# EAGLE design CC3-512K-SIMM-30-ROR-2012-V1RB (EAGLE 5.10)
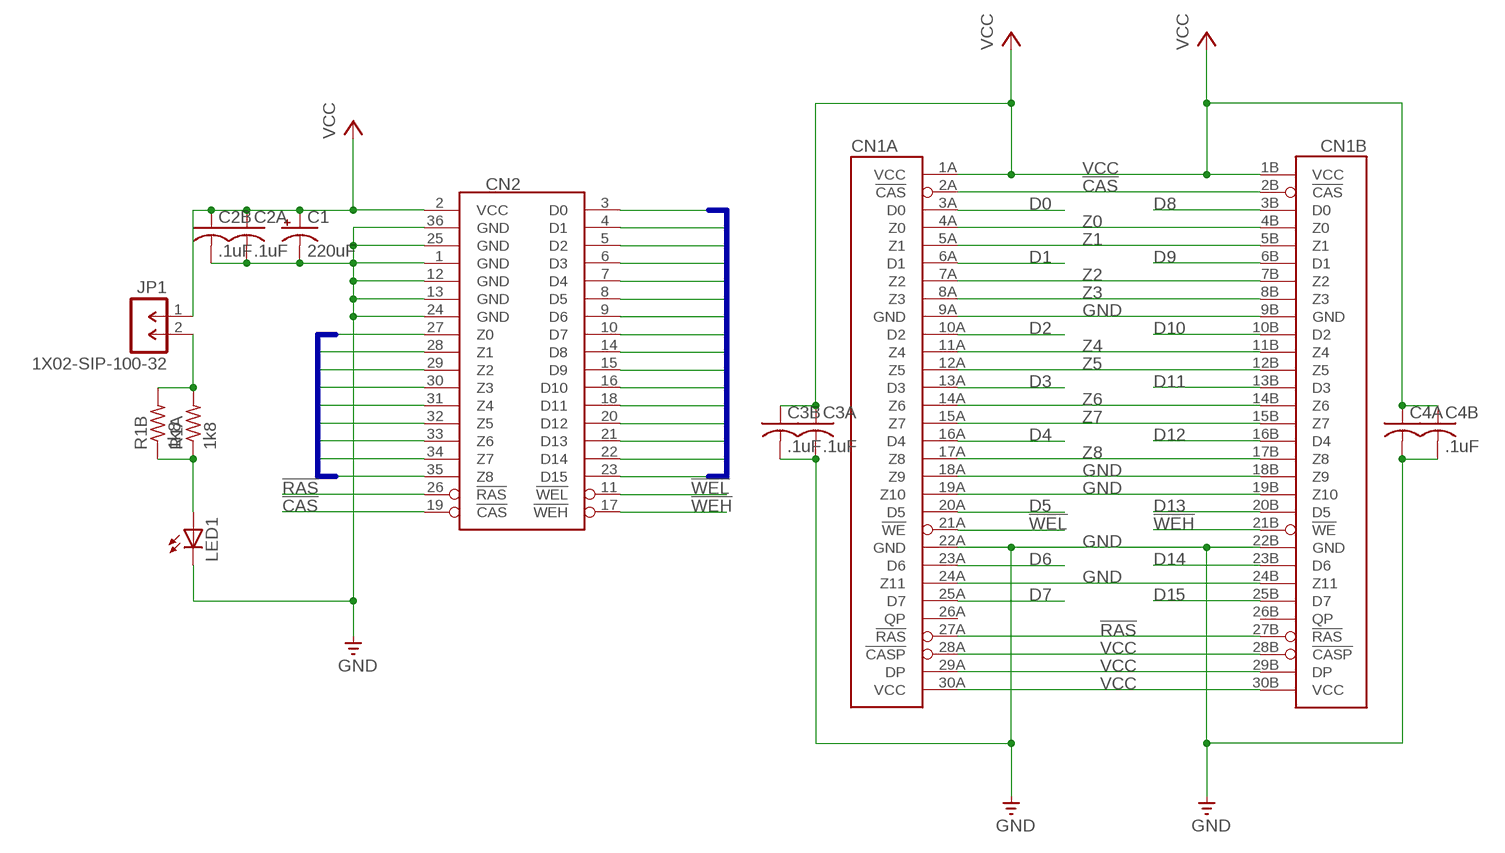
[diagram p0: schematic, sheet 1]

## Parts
C1  220uF  P-CAPACITOR-CPOL-RADIAL-1  [CPOL-RADIAL-1]
C2A  .1uF  NP-CAPACITOR-C050-025X075  [C050-025X075]
C2B  .1uF  NP-CAPACITOR-C1206K  [C1206K]
C3A  .1uF  NP-CAPACITOR-C050-025X075  [C050-025X075]
C3B  .1uF  NP-CAPACITOR-C1206K  [C1206K]
C4A  NP-CAPACITOR-C050-025X075  [C050-025X075]
C4B  .1uF  NP-CAPACITOR-C1206K  [C1206K]
CN1  DUAL-SIMM-30-UNIVERSAL-UNIVERSAL  [DUAL-SIMM-30-UNIVERSAL]
CN2  COCO3-MEMORY-EXPANSION-HEADER  [COCO3-MEMORY-EXPANSION-HEADER]
JP1  1X02-SIP-100-32  [SIL1X02-100]
LED1  LED5MM  [LED5MM]
R1A  1k8  RESISTOR  [0207/10]
R1B  1k8  RESISTOR-R1206  [R1206]

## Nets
!CAS: CN1.2A(A:!CAS) CN1.2B(B:!CAS) CN2.19(!CAS)
!RAS: CN1.27A(A:!RAS) CN1.27B(B:!RAS) CN2.26(!RAS)
!WEH: CN1.21B(B:!WE) CN2.17(!WEH)
!WEL: CN1.21A(A:!WE) CN2.11(!WEL)
D0: CN1.3A(A:D0) CN2.3(D0)
D1: CN1.6A(A:D1) CN2.4(D1)
D2: CN1.10A(A:D2) CN2.5(D2)
D3: CN1.13A(A:D3) CN2.6(D3)
D4: CN1.16A(A:D4) CN2.7(D4)
D5: CN1.20A(A:D5) CN2.8(D5)
D6: CN1.23A(A:D6) CN2.9(D6)
D7: CN1.25A(A:D7) CN2.10(D7)
D8: CN1.3B(B:D0) CN2.14(D8)
D9: CN1.6B(B:D1) CN2.15(D9)
D10: CN1.10B(B:D2) CN2.16(D10)
D11: CN1.13B(B:D3) CN2.18(D11)
D12: CN1.16B(B:D4) CN2.20(D12)
D13: CN1.20B(B:D5) CN2.21(D13)
D14: CN1.23B(B:D6) CN2.22(D14)
D15: CN1.25B(B:D7) CN2.23(D15)
GND [power]: C1.2(-) C2A.2(-) C2B.2(-) C3A.2(-) C3B.2(-) C4A.2(-) C4B.2(-) CN1.9A(A:GND) CN1.9B(B:GND) CN1.18A(A:Z9) CN1.18B(B:Z9) CN1.19A(A:Z10) CN1.19B(B:Z10) CN1.22A(A:GND) CN1.22B(B:GND) CN1.24A(A:Z11) CN1.24B(B:Z11) CN2.1(GND) CN2.12(GND) CN2.13(GND) CN2.24(GND) CN2.25(GND) CN2.36(GND) LED1.K(C)
N$45: LED1.A R1A.1 R1B.1
N$46: JP1.2 R1A.2 R1B.2
VCC [power]: C1.1(+) C2A.1(+) C2B.1(+) C3A.1(+) C3B.1(+) C4A.1(+) C4B.1(+) CN1.1A(A:VCC) CN1.1B(B:VCC) CN1.28A(A:!CASP) CN1.28B(B:!CASP) CN1.29A(A:DP) CN1.29B(B:DP) CN1.30A(A:VCC) CN1.30B(B:VCC) CN2.2(VCC) JP1.1
Z0: CN1.4A(A:Z0) CN1.4B(B:Z0) CN2.27(Z0)
Z1: CN1.5A(A:Z1) CN1.5B(B:Z1) CN2.28(Z1)
Z2: CN1.7A(A:Z2) CN1.7B(B:Z2) CN2.29(Z2)
Z3: CN1.8A(A:Z3) CN1.8B(B:Z3) CN2.30(Z3)
Z4: CN1.11A(A:Z4) CN1.11B(B:Z4) CN2.31(Z4)
Z5: CN1.12A(A:Z5) CN1.12B(B:Z5) CN2.32(Z5)
Z6: CN1.14A(A:Z6) CN1.14B(B:Z6) CN2.33(Z6)
Z7: CN1.15A(A:Z7) CN1.15B(B:Z7) CN2.34(Z7)
Z8: CN1.17A(A:Z8) CN1.17B(B:Z8) CN2.35(Z8)
Unconnected: CN1.26A(A:QP) CN1.26B(B:QP)

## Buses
D[0..15]
Z[0..8]

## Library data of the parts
C1 = GIMEchip-Capacitor:P-CAPACITOR: POLARIZED CAPACITOR
C2A C2B C3A C3B C4A C4B = GIMEchip-Capacitor:NP-CAPACITOR: NON-POLARIZED CAPACITOR
CN1 = GIMEchip-DRAM:DUAL-SIMM-30-UNIVERSAL
CN2 = GIMEchip-TRS-80-CoCo-3-Memory-Expansion-Connector:COCO3-MEMORY-EXPANSION-HEADER: Tandy Color Computer 3 Memory Expansion Connector Tandy Radio Shack TRS-80 Color Computer 3 Memory Expansion Header. CN6, CN5, CN4 on the CoCo 3 Motherboard. These connectors were intended, by Tandy, to upgrade the CoCo 3 from 128k RAM to 512k RAM. Used by third parties for expansion to: 256k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
JP1 = GIMEchip-Header-Generic:1X02: MALE HEADER
LED1 = adafruit:LED: LED
R1A R1B = GIMEchip-Resistor:RESISTOR

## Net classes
0 default: width 0.305 mm, clearance 0.203 mm
1 power: width 0.889 mm, clearance 0.203 mm

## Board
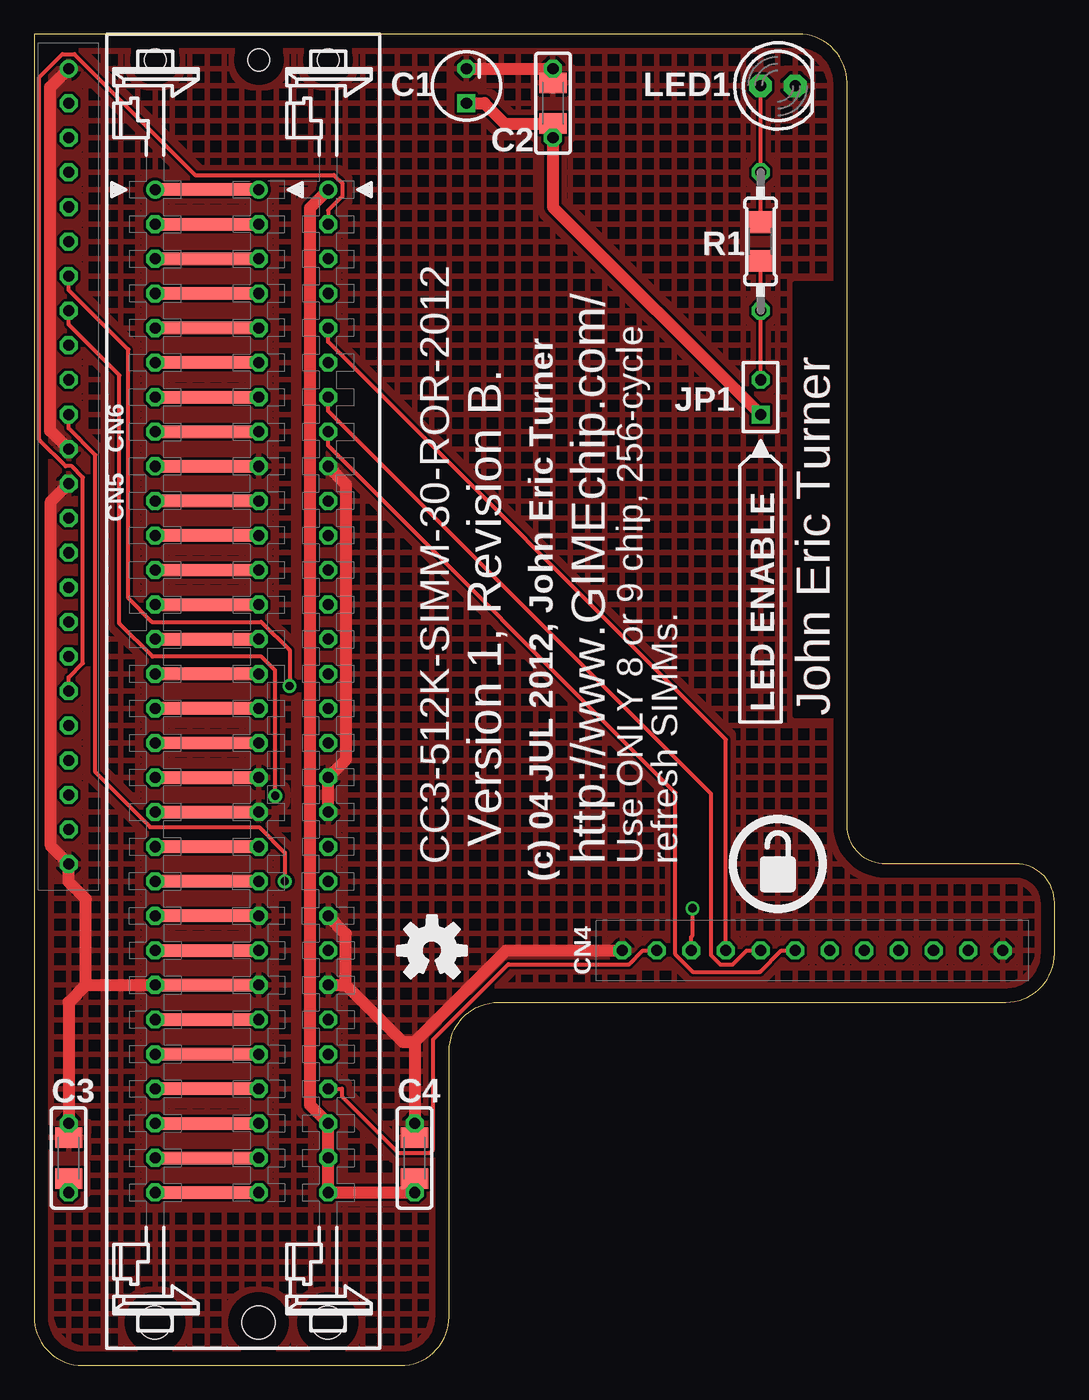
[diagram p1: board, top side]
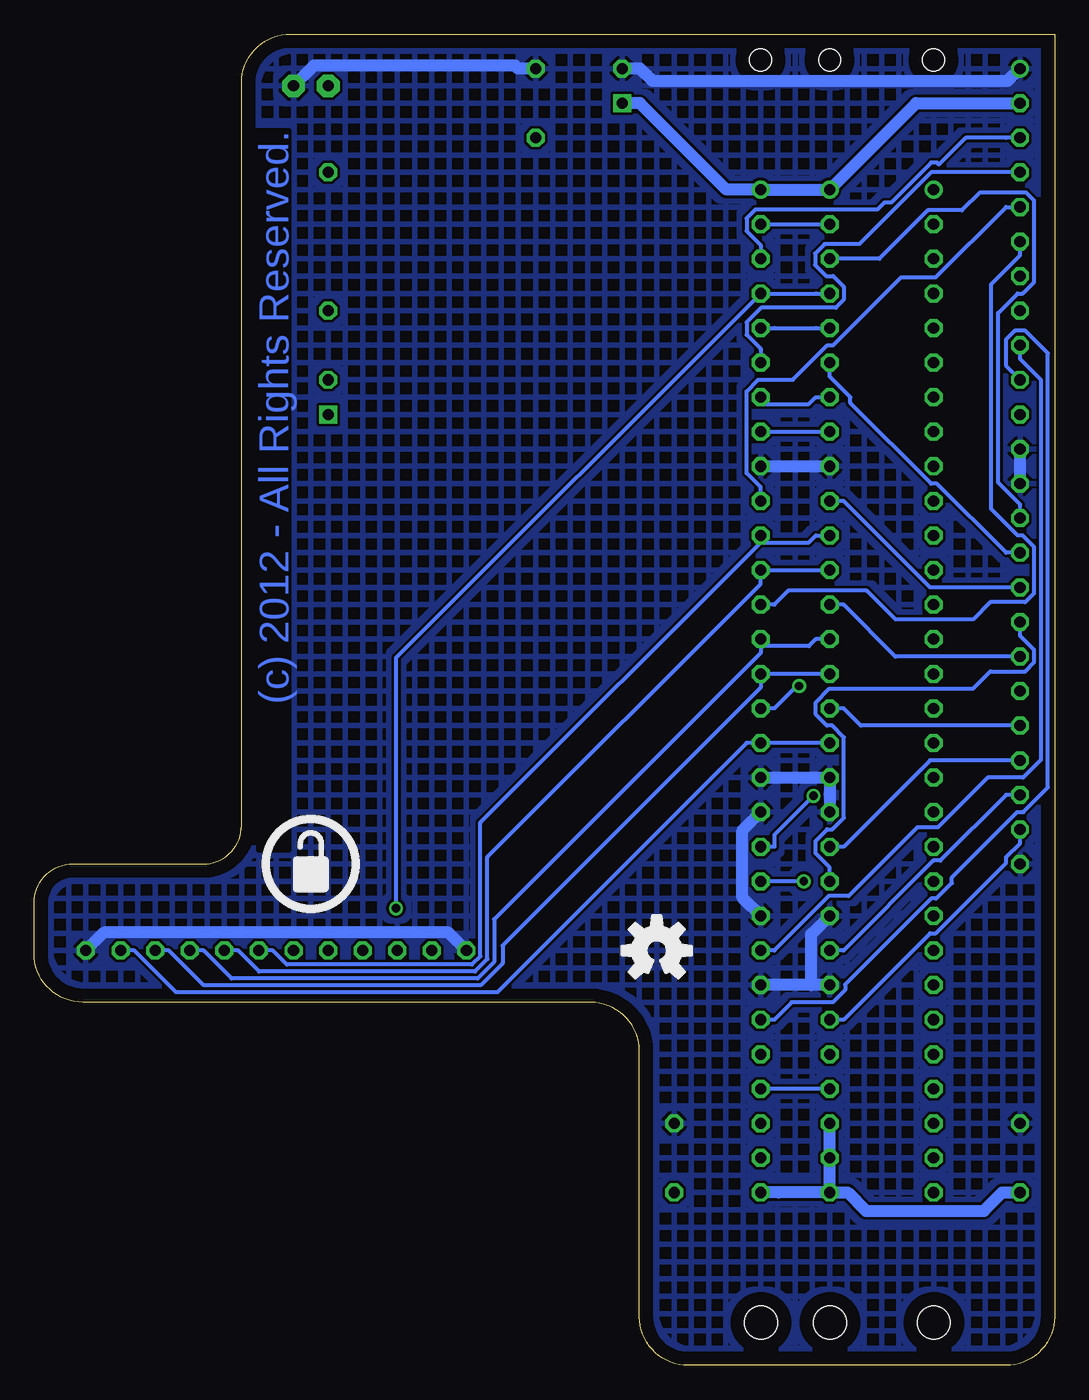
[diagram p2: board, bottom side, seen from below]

Size 74.93 x 97.79 mm. Coordinates in mm from the lower left corner, seen from the top.
Outline: 0,97.79 0,3.59 arc90 3.59,0 26.89,0 arc90 30.48,3.59 30.48,23.08 arc-90 34.07,26.67 71.34,26.67 arc90 74.93,30.26 74.93,33.99 arc90 72.09,36.83 67.31,36.83 62.53,36.83 arc-90 59.69,39.67 59.69,94.2 arc90 56.1,97.79 0,97.79
Copper layers (1*16): Top 0.035mm / dielectric 1.5mm / Bottom 0.035mm
Design rules "default": minimum track width 10mil, minimum drill 24mil, track to track 8mil, track to pad 8mil, pad to pad 8mil, via to via 8mil, smd to smd 8mil, copper to edge 40mil, drill to drill 8mil, minimum pad ring 10mil, minimum via ring 8mil, stop-mask expansion 4mil, vias tented up to drill 0mil, thermal gap 10mil
vRestrict: area 26.7,34.3 to 52.1,87.6

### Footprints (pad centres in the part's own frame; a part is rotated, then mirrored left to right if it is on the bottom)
CPOL-RADIAL-1 = drill 0.813 square: 1 1.27,0 | drill 0.813 octagon: 2 -1.27,0
C050-025X075 = drill 0.813 octagon: 1 -2.54,0; 2 2.54,0
C1206K = smd 1.5 x 2: 1 -1.5,0; 2 1.5,0
DUAL-SIMM-30-UNIVERSAL = drill 0.813 round: 1 -36.83,-3.81; 1A -36.83,8.89; 1B -36.83,3.81 | drill 0.813 octagon: 2 -34.29,-3.81; 2A -34.29,8.89; 2B -34.29,3.81; 3 -31.75,-3.81; 3A -31.75,8.89; 3B -31.75,3.81; 4 -29.21,-3.81; 4A -29.21,8.89; 4B -29.21,3.81; 5 -26.67,-3.81; 5A -26.67,8.89; 5B -26.67,3.81; 6 -24.13,-3.81; 6A -24.13,8.89; 6B -24.13,3.81; 7 -21.59,-3.81; 7A -21.59,8.89; 7B -21.59,3.81; 8 -19.05,-3.81; 8A -19.05,8.89; 8B -19.05,3.81; 9 -16.51,-3.81; 9A -16.51,8.89; 9B -16.51,3.81; 10 -13.97,-3.81; 10A -13.97,8.89; 10B -13.97,3.81; 11 -11.43,-3.81; 11A -11.43,8.89; 11B -11.43,3.81; 12 -8.89,-3.81; 12A -8.89,8.89; 12B -8.89,3.81; 13 -6.35,-3.81; 13A -6.35,8.89; 13B -6.35,3.81; 14 -3.81,-3.81; 14A -3.81,8.89; 14B -3.81,3.81; 15 -1.27,-3.81; 15A -1.27,8.89; 15B -1.27,3.81; 16 1.27,-3.81; 16A 1.27,8.89; 16B 1.27,3.81; 17 3.81,-3.81; 17A 3.81,8.89; 17B 3.81,3.81; 18 6.35,-3.81; 18A 6.35,8.89; 18B 6.35,3.81; 19 8.89,-3.81; 19A 8.89,8.89; 19B 8.89,3.81; 20 11.43,-3.81; 20A 11.43,8.89; 20B 11.43,3.81; 21 13.97,-3.81; 21A 13.97,8.89; 21B 13.97,3.81; 22 16.51,-3.81; 22A 16.51,8.89; 22B 16.51,3.81; 23 19.05,-3.81; 23A 19.05,8.89; 23B 19.05,3.81; 24 21.59,-3.81; 24A 21.59,8.89; 24B 21.59,3.81; 25 24.13,-3.81; 25A 24.13,8.89; 25B 24.13,3.81; 26 26.67,-3.81; 26A 26.67,8.89; 26B 26.67,3.81; 27 29.21,-3.81; 27A 29.21,8.89; 27B 29.21,3.81; 28 31.75,-3.81; 28A 31.75,8.89; 28B 31.75,3.81; 29 34.29,-3.81; 29A 34.29,8.89; 29B 34.29,3.81; 30 36.83,-3.81; 30A 36.83,8.89; 30B 36.83,3.81 | smd 0.914 x 7.62: P$1 -36.83,0; P$2 -34.29,0; P$3 -31.75,0; P$4 -29.21,0; P$5 -26.67,0; P$6 -24.13,0; P$7 -21.59,0; P$8 -19.05,0; P$9 -16.51,0; P$10 -13.97,0; P$11 -11.43,0; P$12 -8.89,0; P$13 -6.35,0; P$14 -3.81,0; P$15 -1.27,0; P$16 1.27,0; P$17 3.81,0; P$18 6.35,0; P$19 8.89,0; P$20 11.43,0; P$21 13.97,0; P$22 16.51,0; P$23 19.05,0; P$24 21.59,0; P$25 24.13,0; P$26 26.67,0; P$27 29.21,0; P$28 31.75,0; P$29 34.29,0; P$30 36.83,0 | hole 2.413: 46.38,-3.835; 46.38,8.865; 46.38,3.785 | hole 1.6: -46.355,-3.81; -46.355,8.89; -46.355,3.81
COCO3-MEMORY-EXPANSION-HEADER = drill 0.813 round: 1 -2.54,30.48 | drill 0.813 octagon: 2 -2.54,27.94; 3 -2.54,25.4; 4 -2.54,22.86; 5 -2.54,20.32; 6 -2.54,17.78; 7 -2.54,15.24; 8 -2.54,12.7; 9 -2.54,10.16; 10 -2.54,7.62; 11 -2.54,5.08; 12 -2.54,2.54; 13 -2.54,0; 14 -2.54,-2.54; 15 -2.54,-5.08; 16 -2.54,-7.62; 17 -2.54,-10.16; 18 -2.54,-12.7; 19 -2.54,-15.24; 20 -2.54,-17.78; 21 -2.54,-20.32; 22 -2.54,-22.86; 23 -2.54,-25.4; 24 -2.54,-27.94; 25 38.1,-34.29; 26 40.64,-34.29; 27 43.18,-34.29; 28 45.72,-34.29; 29 48.26,-34.29; 30 50.8,-34.29; 31 53.34,-34.29; 32 55.88,-34.29; 33 58.42,-34.29; 34 60.96,-34.29; 35 63.5,-34.29; 36 66.04,-34.29
SIL1X02-100 = drill 0.813 square: 1 -1.27,0 | drill 0.813 octagon: 2 1.27,0
LED5MM = drill 0.813 pad 1.676 octagon: A -1.27,0; K 1.27,0
0207/10 = drill 0.813 octagon: 1 -5.08,0; 2 5.08,0
R1206 = smd 1.6 x 1.803: 1 -1.422,0; 2 1.422,0

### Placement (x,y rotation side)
C1  31.75,93.98 270 top
C2A  38.1,92.71 90 top
C2B  38.1,92.71 90 top
C3A  2.54,15.24 90 top
C3B  2.54,15.24 90 top
C4A  27.94,15.24 90 top
C4B  27.94,15.24 90 top
CN1  12.7,49.53 270 top
CN2  5.08,64.77 0 top
JP1  53.34,71.12 90 top
LED1  54.61,93.98 0 top
R1A  53.34,82.55 270 top
R1B  53.34,82.55 270 top
U$1  [OSHWLOGO_0.3]  54.61,36.83 0 top
U$2  [OSHWLOGO_0.3]  54.61,36.83 0 bottom
U$3  [OSHWLOGO_TOL_0.2]  29.21,30.48 0 top
U$4  [OSHWLOGO_TOL_0.2]  29.21,30.48 0 bottom

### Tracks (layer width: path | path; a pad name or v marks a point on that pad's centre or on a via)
!CAS
  Top 0.305: CN1.2A 21.59,84.84 22.63,85.88 22.63,86.82 22.01,87.44 11.84,87.44 2.96,96.31 2.08,96.31 0.39,94.62 0.39,67.98 2.33,66.04 2.77,66.04 3.58,65.23 3.58,51.59 2.54,50.55 CN2.19
  Bottom 0.305: CN1.2A CN1.2B
!RAS
  Top 0.305: CN1.27A 22.61,20.32 22.61,19.75 26.72,15.63 29.09,15.63 29.3,15.84 29.3,23.94 34.82,29.46 43.69,29.46 44.7,30.48 CN2.26
  Bottom 0.305: CN1.27B CN1.27A
!WEH
  Bottom 0.305: CN1.21B 16.51,36.58 17.55,37.62 17.55,38.51 16.69,39.37 16.34,39.37 15.48,40.23 15.48,46.13 16.34,46.99 16.71,46.99 17.53,47.81 17.53,48.71 16.53,49.71 5.99,49.71 4.72,50.98 2.17,50.98 1.5,51.65 1.5,52.56 2.54,53.59 CN2.17
!WEL  (via drill 0.61 pad 1.02)
  Top 0.305: v18.41,35.56 18.41,37.66 16.52,39.55 8.53,39.55 4.5,43.58 4.5,66.87 2.54,68.83 CN2.11
  Bottom 0.305: v18.41,35.56 20.57,35.56 CN1.21A
D0
  Bottom 0.305: CN1.3A 21.59,82.3 22.61,83.32 22.61,84.25 21.96,84.9 13.01,84.9 12.5,85.41 12,85.41 9.06,88.35 8.64,88.35 8.49,88.2 6.52,90.17 3.56,90.17 CN2.3
D1
  Bottom 0.305: CN1.6A 21.59,74.68 22.61,75.7 22.61,76.61 21.54,77.69 16.06,77.69 15.49,78.27 15.49,79.24 16.26,80.01 16.76,80.01 17.58,80.82 17.58,81.66 16.88,82.36 14.33,82.36 9.06,87.63 CN2.4
D2
  Bottom 0.305: CN1.10A 21.59,64.52 22.61,65.53 22.61,71.54 21.76,72.39 19.22,72.39 16.68,74.93 16.26,74.93 11.27,79.92 8.73,79.92 3.56,85.09 CN2.5
D3
  Bottom 0.305: CN1.13A 20.57,55.88 19.54,56.91 13.8,56.91 11.68,54.79 5.99,54.79 4.72,56.06 2.17,56.06 1.5,56.73 1.5,60.12 2.34,60.96 2.71,60.96 4.67,62.91 4.67,79.41 2.54,81.53 CN2.6
D4  (via drill 0.61 pad 1.02)
  Top 0.305: v18.76,49.9 18.76,52.53 16.68,54.61 8.66,54.61 6.92,56.35 6.92,74.62 2.54,78.99 CN2.7
  Bottom 0.305: CN1.16A 20.57,48.26 18.93,49.9 v18.76,49.9
D5  (via drill 0.61 pad 1.02)
  Top 0.305: CN2.8 2.54,76.45 6.26,72.73 6.26,54.51 8.7,52.07 16.69,52.07 17.7,51.06 v17.7,41.84
  Bottom 0.305: CN1.20A 20.57,38.1 20.57,38.97 v17.7,41.84
D6
  Bottom 0.305: CN2.9 2.54,73.91 0.99,72.37 0.99,44.51 2.32,43.18 4.91,43.18 8.57,39.52 10.07,39.52 15.12,34.47 16.58,34.47 20.57,30.48 CN1.23A
D7
  Bottom 0.305: CN2.10 3.59,73.44 3.59,75.33 2.92,76 2.14,76 0.49,74.34 0.49,42.46 2.3,40.64 2.74,40.64 7.54,35.84 7.54,35.44 8.7,34.29 9.07,34.29 15.39,27.98 15.39,27.57 16.29,26.67 19.3,26.67 20.57,25.4 CN1.25A
D8
  Bottom 0.305: CN1.3B 12.87,81.28 9.31,84.84 6.81,84.84 5.51,86.14 2.08,86.14 1.5,85.56 1.5,79.58 2.34,78.74 2.71,78.74 4.15,77.31 4.15,64.85 2.54,63.25 CN2.14
D9
  Bottom 0.305: CN1.6B 16.51,72.64 14.99,71.12 14.99,70.7 9.06,64.77 8.64,64.77 3.56,59.69 CN2.15
D10
  Bottom 0.305: CN1.10B 15.49,63.5 9.14,57.15 3.56,57.15 CN2.16
D11
  Bottom 0.305: CN1.13B 15.49,55.88 11.68,52.07 CN2.18
D12
  Bottom 0.305: CN1.16B 15.49,48.26 14.22,46.99 CN2.20
D13
  Bottom 0.305: CN1.20B 15.49,38.1 9.14,44.45 CN2.21
D14
  Bottom 0.305: CN1.23B 15.49,30.48 8.9,37.08 8.39,37.08 3.56,41.91 CN2.22
D15
  Bottom 0.305: CN1.25B 15.49,25.4 9.14,31.75 8.72,31.75 3.56,36.91 3.56,37.34 2.54,38.35 CN2.23
GND
  Top 0.889: C3B.2 C3A.2 2.54,26.67 3.81,27.94 | 27.94,23.76 C4A.2 C4B.2 | CN2.25 34.66,30.48 27.94,23.76 | 22.9,27.94 27.08,23.76 27.94,23.76 | 22.9,27.94 22.9,31.71 CN1.22A | 22.9,27.94 22.62,27.94 CN1.24A | C1.2 33.06,95.25 C2A.2 C2B.2 | CN1.9A 22.92,64.71 22.92,44.51 CN1.18A CN1.19A | CN2.1 1.19,93.9 1.19,68.66 CN2.12 | CN2.13 1.23,63.46 1.23,38.14 CN2.24 2.54,35.52 3.81,34.25 3.81,27.94 | 3.81,27.94 CN1.24B
  Bottom 0.889: C1.2 30.44,95.25 29.52,94.33 3.46,94.33 CN2.1 | CN1.22A 22.93,34.36 22.93,39.3 CN1.19A | CN1.18A CN1.18B 16.51,41.95 CN1.19B | CN2.13 CN2.12 | CN2.25 44.5,31.8 69.8,31.8 CN2.36 | 17.87,27.94 CN1.24A | CN1.24B 17.87,27.94 | 17.87,27.94 17.87,31.66 CN1.22B | C2A.2 38.75,95.25 39.41,95.25 39.63,95.47 54.39,95.47 LED1.K | CN1.9A CN1.9B
  pour Top (hatched): -1.27,-2.54 76.2,-2.54 76.2,100.33 -1.27,100.33
  pour Bottom (hatched): -1.27,100.33 77.47,100.33 77.47,-2.54 -1.27,-2.54
N$45
  Top 0.305: R1B.1 R1A.1 LED1.A
N$46
  Top 0.305: R1B.2 R1A.2 JP1.2
VCC
  Top 0.889: C1.1 33.06,92.71 34.56,91.21 C2B.1 C2A.1 38.1,85.09 JP1.1 | CN1.1A 20.27,85.03 20.27,19.11 CN1.28A CN1.29A 21.59,14.59 21.59,13.93 CN1.30A C4A.1 C4B.1 | C3A.1 C3B.1
  Bottom 0.889: C1.1 30.44,92.71 24.09,86.36 CN1.1A CN1.1B 10.16,92.71 CN2.2 | C3A.1 3.85,12.7 5.19,11.36 13.86,11.36 15.2,12.7 CN1.30B | CN1.30B 20.28,12.7 CN1.30A | CN1.30B CN1.29B CN1.28B
Z0  (via drill 0.61 pad 1.02)
  Top 0.305: v48.35,33.58 48.35,31.59 48.26,31.5 CN2.27
  Bottom 0.305: v48.35,33.58 48.35,51.98 CN1.4A 17.53,78.74 CN1.4B
Z1
  Top 0.305: CN1.5A 21.59,75.18 50.8,45.97 CN2.28
  Bottom 0.305: CN1.5B 17.53,76.2 20.57,76.2 CN1.5A
Z2
  Top 0.305: CN1.7A 21.59,70.1 49.71,41.98 49.71,30.12 50.39,29.44 51.29,29.44 52.32,30.48 CN2.29
  Bottom 0.305: CN1.7B 17.53,71.12 18.03,70.61 21.59,70.61 CN1.7A
Z3
  Top 0.305: CN1.8A 21.59,67.56 47.09,42.06 47.09,30.18 48.34,28.92 53.31,28.92 54.86,30.48 CN2.30
  Bottom 0.305: CN1.8A CN1.8B
Z4
  Bottom 0.305: CN2.31 57.4,30.48 56.37,29.44 42.78,29.44 42.16,30.06 42.16,39.88 21.59,60.45 | CN1.11B 17.53,60.96 18.03,60.45 21.59,60.45 | 21.59,60.45 CN1.11A
Z5
  Bottom 0.305: CN2.32 59.94,30.48 58.4,28.94 42.57,28.94 41.66,29.85 41.66,37.34 21.59,57.4 CN1.12A 17.53,58.42 CN1.12B
Z6
  Bottom 0.305: CN1.14B 17.53,53.34 18.03,52.83 21.59,52.83 | 21.59,52.83 21.59,52.32 41.15,32.77 41.15,29.64 42.36,28.43 60.43,28.43 62.48,30.48 CN2.33 | 21.59,52.83 CN1.14A
Z7
  Bottom 0.305: CN1.15B 17.53,50.8 20.57,50.8 CN1.15A 21.59,49.78 40.53,30.84 40.53,29.53 42.15,27.92 62.46,27.92 65.02,30.48 CN2.34
Z8
  Bottom 0.305: CN1.17B CN1.17A 22.61,45.72 40.92,27.41 64.49,27.41 67.56,30.48 CN2.35

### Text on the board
Top: John Eric Turner
Bottom: (c) 2012 - All Rights Reserved.
tPlace: Use ONLY 8 or 9 chip, 256-cycle | refresh SIMMs.
tNames: C1 | LED1 | C2 | C1 | CN1 | LED1 | C2A | C2B | R1A | R1 | R1B | RESISTOR | RESISTOR-R1206 | 1X02-SIP-100-32 | JP1 | JP1 | CN6 | CN5 | C3B | C3A | C4A | CN2 | C4B | LED ENABLE | John Eric Turner | Version 1, Revision B. | CC3-512K-SIMM-30-ROR-2012 | http://www.GIMEchip.com/ | (c) 04 JUL 2012, John Eric Turner | CN4 | C3 | C4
